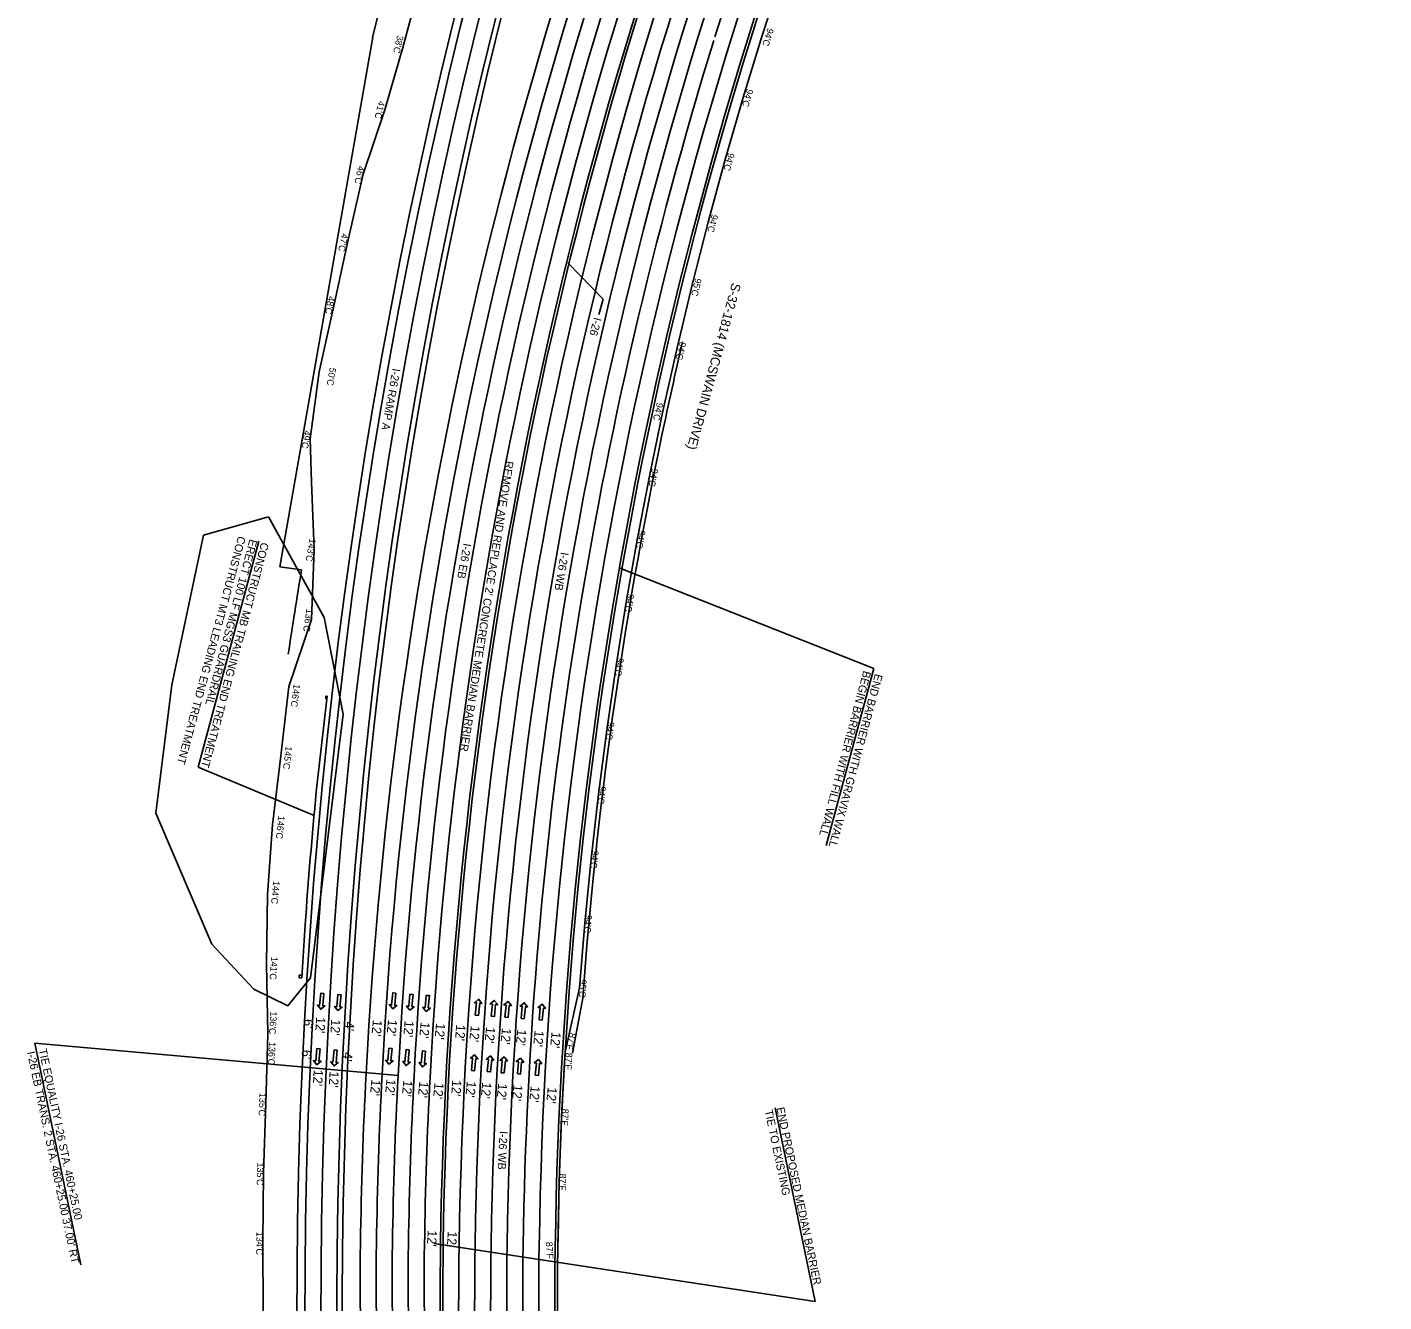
# Model space of a CAD drawing. Extents: x 1966090 to 1975830, y 788086 to 801233.
# Drawn here: x 1966090 to 1967107, y 790893 to 791849 of the extents above; entities that cross this region are included whole.
import ezdxf

# ---------------------------------------------------------------- set-up
doc = ezdxf.new("R2010")
doc.units = 0
for name, color, linetype in [('BR_PRESTRESSED BEAM', 7, 'Continuous'), ('BR_PROPOSED_DRAINAGE', 7, 'Continuous'), ('BR_REBAR', 7, 'Continuous'), ('RD_EX_Driveway_txCode', 7, 'Continuous'), ('RD_EX_RW_TX', 7, 'Continuous'), ('RD_EX_SU_Gas', 7, 'Continuous'), ('RD_EX_SU_H2O', 7, 'Continuous'), ('RD_EX_TX_Dam_ELEV', 7, 'Continuous'), ('RD_PD_PaveShd', 7, 'Continuous'), ('RD_PD_SuperShp1', 7, 'Continuous'), ('RD_Sketch6', 7, 'Continuous'), ('RD_Sketch8', 7, 'Continuous')]:
    doc.layers.add(name, color=color, linetype=linetype)

msp = doc.modelspace()

# ---------------------------------------------------------------- linework, layer by layer
at = {"layer": 'BR_PRESTRESSED BEAM'}
for p, q in [((1966306.7, 791275.8), (1966314.8, 791347.4)), ((1966314.8, 791347.4), (1966313.8, 791347.5)), ((1966313.8, 791347.5), (1966313.8, 791345.5)), ((1966313.8, 791345.5), (1966314.6, 791345.4)), ((1966314.6, 791345.4), (1966314.8, 791347.4)), ((1966298.4, 791176.2), (1966295.8, 791136.3)), ((1966293.8, 791136.4), (1966293.9, 791138.4)), ((1966293.9, 791138.4), (1966295.9, 791138.3)), ((1966295.9, 791138.3), (1966295.8, 791136.3)), ((1966295.8, 791136.3), (1966293.8, 791136.4))]:
    msp.add_line(p, q, dxfattribs=at)
msp.add_arc((1970298.2, 790890.8), 4010, 174.4907, 175.9195, dxfattribs=at)
at = {"layer": 'BR_PROPOSED_DRAINAGE'}
for p, q in [((1966385.1, 791884.3), (1966372.2, 791835.5)), ((1966655.8, 791888.9), (1966640.9, 791842.7)), ((1966640.9, 791842.7), (1966626.7, 791796.2)), ((1966372.2, 791835.5), (1966358.2, 791786.9)), ((1966626.7, 791796.2), (1966613.2, 791749.6)), ((1966358.2, 791786.9), (1966341.9, 791738.7)), ((1966613.2, 791749.6), (1966600.5, 791702.7)), ((1966341.9, 791738.7), (1966330.6, 791689.4)), ((1966600.5, 791702.7), (1966588.4, 791655.7)), ((1966330.6, 791689.4), (1966319.8, 791640)), ((1966588.4, 791655.7), (1966577.1, 791608.5)), ((1966319.8, 791640), (1966308.9, 791590.5)), ((1966577.1, 791608.5), (1966566.5, 791561.1)), ((1966308.9, 791590.5), (1966302.1, 791540.3)), ((1966566.5, 791561.1), (1966556.6, 791513.6)), ((1966303.2, 791507.8), (1966302.1, 791540.3)), ((1966303.2, 791507.8), (1966305.2, 791457.4)), ((1966556.6, 791513.6), (1966547.5, 791465.9)), ((1966547.5, 791465.9), (1966539, 791418)), ((1966305.2, 791457.4), (1966303.2, 791404.9)), ((1966539, 791418), (1966531.4, 791370.1)), ((1966303.2, 791404.9), (1966286.2, 791354.7)), ((1966531.4, 791370.1), (1966524.4, 791322)), ((1966286.2, 791354.7), (1966280.2, 791302.8)), ((1966524.4, 791322), (1966518.2, 791273.9)), ((1966280.2, 791302.8), (1966274, 791250.9)), ((1966518.2, 791273.9), (1966512.7, 791225.6)), ((1966274, 791250.9), (1966270.2, 791198.8)), ((1966512.7, 791225.6), (1966507.9, 791177.3)), ((1966270.2, 791198.8), (1966269.4, 791146.6)), ((1966507.9, 791177.3), (1966503.9, 791128.9)), ((1966269.4, 791146.6), (1966270.4, 791094.3)), ((1966503.9, 791128.9), (1966493.2, 791080.9)), ((1966270.4, 791094.3), (1966268.8, 791042.2)), ((1966493.2, 791080.9), (1966490.6, 791032.3)), ((1966268.8, 791042.2), (1966267.2, 790990.2)), ((1966490.6, 791032.3), (1966488.8, 790983.7)), ((1966267.2, 790990.2), (1966266.7, 790938.1)), ((1966488.8, 790983.7), (1966487.8, 790935)), ((1966266.7, 790938.1), (1966266.9, 790886.1))]:
    msp.add_line(p, q, dxfattribs=at)
msp.add_arc((1969885.9, 790887.5), 3398.5, 179.1982, 182.2683, dxfattribs=at)
at = {"layer": 'BR_REBAR'}
for centre, radius, start, end in [((1969675.5, 790890.4), 3190, 157.1374, 179.2174), ((1969675.5, 790890.4), 3188, 157.1374, 179.2164), ((1969885.9, 790887.5), 3400.5, 179.1982, 182.2683), ((1969885.9, 790887.5), 3398.5, 179.1982, 182.2663)]:
    msp.add_arc(centre, radius, start, end, dxfattribs=at)
at = {"layer": 'RD_EX_Driveway_txCode'}
for points in [[(1966312.4, 791124.6), (1966310, 791124.8), (1966309.1, 791115.7), (1966307.5, 791115.9), (1966310.1, 791112.8), (1966313.2, 791115.3), (1966311.5, 791115.5)], [(1966325.3, 791123.6), (1966322.9, 791123.9), (1966322, 791114.7), (1966320.4, 791114.9), (1966322.9, 791111.8), (1966326, 791114.4), (1966324.4, 791114.5)], [(1966366.4, 791124.9), (1966364, 791125.1), (1966363.1, 791116), (1966361.5, 791116.1), (1966364.1, 791113), (1966367.2, 791115.6), (1966365.5, 791115.7)], [(1966379.3, 791123.9), (1966376.9, 791124.1), (1966376, 791115), (1966374.4, 791115.2), (1966376.9, 791112.1), (1966380, 791114.6), (1966378.4, 791114.8)], [(1966391.5, 791123), (1966389.1, 791123.2), (1966388.2, 791114.1), (1966386.6, 791114.2), (1966389.1, 791111.1), (1966392.2, 791113.7), (1966390.6, 791113.9)], [(1966425.9, 791108.4), (1966428.3, 791108.2), (1966429.2, 791117.3), (1966430.8, 791117.2), (1966428.3, 791120.3), (1966425.2, 791117.7), (1966426.8, 791117.6)], [(1966437.8, 791107.5), (1966440.2, 791107.3), (1966441.1, 791116.4), (1966442.7, 791116.3), (1966440.1, 791119.4), (1966437, 791116.8), (1966438.7, 791116.7)], [(1966448, 791106.8), (1966450.4, 791106.5), (1966451.3, 791115.7), (1966452.9, 791115.5), (1966450.4, 791118.6), (1966447.3, 791116), (1966448.9, 791115.9)], [(1966460.2, 791105.8), (1966462.6, 791105.6), (1966463.5, 791114.7), (1966465.1, 791114.6), (1966462.6, 791117.7), (1966459.5, 791115.1), (1966461.1, 791115)], [(1966473.7, 791104.8), (1966476.1, 791104.6), (1966477, 791113.7), (1966478.6, 791113.6), (1966476, 791116.7), (1966473, 791114.1), (1966474.6, 791114)], [(1966309.5, 791083.1), (1966307.1, 791083.3), (1966306.3, 791074.2), (1966304.6, 791074.3), (1966307.2, 791071.2), (1966310.3, 791073.8), (1966308.6, 791073.9)], [(1966322.4, 791082.1), (1966320, 791082.3), (1966319.1, 791073.2), (1966317.5, 791073.4), (1966320, 791070.3), (1966323.1, 791072.8), (1966321.5, 791073)], [(1966363.5, 791083.3), (1966361.1, 791083.6), (1966360.3, 791074.4), (1966358.6, 791074.6), (1966361.2, 791071.5), (1966364.3, 791074), (1966362.6, 791074.2)], [(1966376.4, 791082.4), (1966374, 791082.6), (1966373.1, 791073.5), (1966371.5, 791073.6), (1966374, 791070.5), (1966377.1, 791073.1), (1966375.5, 791073.2)], [(1966388.6, 791081.4), (1966386.2, 791081.7), (1966385.3, 791072.5), (1966383.7, 791072.7), (1966386.3, 791069.6), (1966389.3, 791072.2), (1966387.7, 791072.3)], [(1966423, 791066.9), (1966425.4, 791066.7), (1966426.3, 791075.8), (1966427.9, 791075.6), (1966425.4, 791078.7), (1966422.3, 791076.2), (1966423.9, 791076)], [(1966434.9, 791066), (1966437.3, 791065.8), (1966438.2, 791074.9), (1966439.8, 791074.7), (1966437.2, 791077.8), (1966434.2, 791075.3), (1966435.8, 791075.1)], [(1966445.2, 791065.2), (1966447.5, 791065), (1966448.4, 791074.1), (1966450, 791074), (1966447.5, 791077.1), (1966444.4, 791074.5), (1966446, 791074.4)], [(1966457.4, 791064.3), (1966459.7, 791064.1), (1966460.6, 791073.2), (1966462.2, 791073), (1966459.7, 791076.1), (1966456.6, 791073.6), (1966458.2, 791073.4)], [(1966470.8, 791063.3), (1966473.2, 791063.1), (1966474.1, 791072.2), (1966475.7, 791072), (1966473.2, 791075.1), (1966470.1, 791072.6), (1966471.7, 791072.4)]]:
    msp.add_lwpolyline(points, close=True, dxfattribs=at)
at = {"layer": 'RD_EX_SU_Gas'}
for centre, radius, start, end in [((1970298.2, 790890.8), 3988, 153.1374, 186.3991), ((1969675.5, 790890.4), 3312, 157.822, 177.0114), ((1969675.5, 790890.4), 3300, 157.822, 177.0114), ((1969675.5, 790890.4), 3214, 157.1374, 162.7868), ((1969675.5, 790890.4), 3250, 157.8325, 179.1982), ((1969675.5, 790890.4), 3238, 157.8325, 179.1982), ((1969675.5, 790890.4), 3226, 157.8325, 179.1982), ((1969675.5, 790890.4), 3214, 162.8366, 179.1982), ((1969675.5, 790890.4), 3312, 177.0114, 179.1982), ((1969675.5, 790890.4), 3300, 177.0114, 179.1982), ((1968216.3, 790910.8), 1852.7, 179.1982, 183.4866), ((1968216.3, 790910.8), 1840.7, 179.1982, 183.4866), ((1969885.9, 790887.5), 3460.5, 179.1982, 191.7117), ((1969885.9, 790887.5), 3448.5, 179.1982, 191.7117), ((1969885.9, 790887.5), 3436.5, 179.1982, 184.4912), ((1969885.9, 790887.5), 3424.5, 179.1982, 184.4912)]:
    msp.add_arc(centre, radius, start, end, dxfattribs=at)
at = {"layer": 'RD_EX_TX_Dam_ELEV'}
for p, q in [((1966349, 791841.3), (1966279.3, 791444.3)), ((1966565.2, 791540.7), (1966565.8, 791543.2)), ((1966295.6, 791442.1), (1966279.3, 791444.3)), ((1966506.4, 791121.2), (1966498.7, 791079.8))]:
    msp.add_line(p, q, dxfattribs=at)
for centre, radius, start, end in [((1970298.2, 790890.8), 4062, 153.0951, 166.4711), ((1969675.5, 790890.4), 3177.5, 166.8537, 168.1442), ((1969675.5, 790890.4), 3177.5, 168.1907, 175.8341), ((1969666.1, 790880.5), 3416.9, 170.5396, 171.6135)]:
    msp.add_arc(centre, radius, start, end, dxfattribs=at)
at = {"layer": 'RD_PD_PaveShd'}
msp.add_line((1966401.8, 790936.2), (1966399.8, 790936.3), dxfattribs=at)
for centre, radius, start, end in [((1970298.2, 790890.8), 4006, 153.1374, 186.3991), ((1970298.2, 790890.8), 3972, 153.1374, 186.1282), ((1969675.5, 790890.4), 3336, 157.1374, 177.0114), ((1969675.5, 790890.4), 3276, 157.1374, 179.1982), ((1969675.5, 790890.4), 3274, 157.1374, 179.1982), ((1969675.5, 790890.4), 3190, 157.1374, 179.2174), ((1969675.5, 790890.4), 3336, 177.0114, 179.1982), ((1968216.3, 790910.8), 1876.7, 179.1982, 183.4866), ((1969675.5, 790890.4), 3276, 179.1982, 191.7117), ((1969675.5, 790890.4), 3274, 179.1982, 191.7117), ((1969885.9, 790887.5), 3400.5, 179.1982, 182.2683)]:
    msp.add_arc(centre, radius, start, end, dxfattribs=at)
at = {"layer": 'RD_PD_SuperShp1'}
msp.add_arc((1966773.3, 790734.6), 333.5, 177.186, 177.186, dxfattribs=at)
at = {"layer": 'RD_Sketch6'}
for p, q in [((1966521.6, 791645.1), (1966495.2, 791672.3)), ((1966518.5, 791633.5), (1966521.6, 791645.1)), ((1966263.7, 791463.6), (1966218.1, 791294.3)), ((1966533.8, 791443.6), (1966724.5, 791368.2)), ((1966688.8, 791235.5), (1966724.5, 791368.2)), ((1966218.1, 791294.3), (1966305.1, 791258.1)), ((1966095.7, 791087.4), (1966368, 791063.1)), ((1966130.2, 790921.1), (1966095.7, 791087.4)), ((1966680.7, 790893.7), (1966650.6, 791038.9)), ((1966395, 790937.3), (1966680.7, 790893.7))]:
    msp.add_line(p, q, dxfattribs=at)
msp.add_lwpolyline([(1966270.9, 791481.9), (1966312.5, 791406.4), (1966326.9, 791334), (1966302.4, 791136.4), (1966285.3, 791115.4), (1966259.8, 791127.8), (1966228.5, 791161.6), (1966186.5, 791259.7), (1966198.5, 791356), (1966222.3, 791468.1)], close=True, dxfattribs=at)
at = {"layer": 'RD_Sketch8'}
for centre, radius, start, end in [((1970298.2, 790890.8), 4000, 153.1374, 186.3991), ((1970298.2, 790890.8), 3976, 153.1374, 186.1303), ((1969675.5, 790890.4), 3324, 157.1374, 177.0114), ((1969675.5, 790890.4), 3288, 157.1374, 177.0114), ((1969675.5, 790890.4), 3262, 157.1374, 179.1982), ((1969675.5, 790890.4), 3202, 157.1374, 179.1982), ((1969675.5, 790890.4), 3324, 177.0114, 179.1982), ((1969675.5, 790890.4), 3288, 177.0114, 179.1982), ((1968216.3, 790910.8), 1864.7, 179.1982, 183.4866), ((1968216.3, 790910.8), 1828.7, 179.1982, 183.4866), ((1969885.9, 790887.5), 3472.5, 179.1982, 191.7117), ((1969885.9, 790887.5), 3412.5, 179.1982, 184.4912)]:
    msp.add_arc(centre, radius, start, end, dxfattribs=at)

# ---------------------------------------------------------------- texts
at = {"layer": 'RD_EX_Driveway_txCode'}
for s, height, rotation, p in [('I-26 RAMP A', 6, 259.7492, (1966363.9, 791593.5)), ("REMOVE AND REPLACE 2' CONCRETE MEDIAN BARRIER", 6, 261.0168, (1966448.7, 791524.1)), ("6'", 7, 269.0379, (1966297.3, 791105.4)), ("12'", 7, 266.9771, (1966306.6, 791107.1)), ("12'", 7, 266.9771, (1966317.9, 791105.4)), ("4'", 7, 266.9056, (1966328.3, 791103.6)), ("12'", 7, 264.5562, (1966349.2, 791105)), ("12'", 7, 264.5562, (1966360.5, 791105.3)), ("12'", 7, 264.5562, (1966373, 791104.4)), ("12'", 7, 264.5562, (1966385, 791103.5)), ("12'", 7, 264.5562, (1966396.5, 791102.6)), ("12'", 7, 266.5124, (1966411.5, 791101.4)), ("12'", 7, 264.5562, (1966422.5, 791100.7)), ("12'", 7, 264.5562, (1966434, 791099.8)), ("12'", 7, 264.5562, (1966445.9, 791098.9)), ("12'", 7, 264.5562, (1966457.4, 791098)), ("12'", 7, 264.5562, (1966470.4, 791097.1)), ("12'", 7, 264.5562, (1966483.1, 791096.1)), ("6'", 7, 269.0379, (1966295.9, 791082.4)), ("4'", 7, 266.9056, (1966326.9, 791080.7)), ("12'", 7, 266.9771, (1966304.8, 791067.6)), ("12'", 7, 266.9771, (1966316.7, 791066.4)), ("12'", 7, 264.5562, (1966348.1, 791060.4)), ("12'", 7, 264.5562, (1966359.4, 791060.7)), ("12'", 7, 264.5562, (1966372, 791059.8)), ("12'", 7, 264.5562, (1966384, 791058.9)), ("12'", 7, 264.5562, (1966395.4, 791058)), ("12'", 7, 266.5124, (1966408.6, 791059.9)), ("12'", 7, 264.5562, (1966419.6, 791059.1)), ("12'", 7, 264.5562, (1966431.1, 791058.3)), ("12'", 7, 264.5562, (1966443, 791057.4)), ("12'", 7, 264.5562, (1966454.5, 791056.5)), ("12'", 7, 264.5562, (1966467.5, 791055.5)), ("12'", 7, 264.5562, (1966480.2, 791054.6)), ("12'", 7, 266.5124, (1966390.3, 790947.3)), ("12'", 7, 266.5124, (1966405.3, 790946.6))]:
    msp.add_text(s, height=height, rotation=rotation, dxfattribs=at).set_placement(p)
at = {"layer": 'RD_EX_RW_TX'}
for s, rotation, p in [("38'C", 256.4711, (1966367.4, 791843.1)), ("94'C", 252.5781, (1966644.9, 791848.5)), ("94'C", 253.4528, (1966629.5, 791803)), ("41'C", 257.1873, (1966353.4, 791794)), ("94'C", 254.3276, (1966615.5, 791755.1)), ("46'C", 257.9035, (1966338.1, 791745.2)), ("94'C", 255.2023, (1966603.1, 791708.9)), ("47'C", 258.6197, (1966325.8, 791694.5)), ("95'C", 256.0771, (1966590.8, 791661.1)), ("48'C", 259.3359, (1966315.7, 791647.6)), ("94'C", 256.9518, (1966579.1, 791613.3)), ("50'C", 260.0521, (1966316.8, 791594)), ("94'C", 257.8265, (1966561.9, 791567.8)), ("49'C", 260.7683, (1966297.7, 791546.9)), ("94'C", 258.7013, (1966558.2, 791518.4)), ("143'C", 260.4508, (1966301.6, 791465.8)), ("94'C", 259.576, (1966548.6, 791472.2)), ("94'C", 260.4508, (1966540.1, 791424.4)), ("136'C", 261.3255, (1966299.4, 791413.2)), ("94'C", 261.3255, (1966532.3, 791376.4)), ("146'C", 262.2003, (1966289.8, 791356.7)), ("94'C", 262.2003, (1966525.3, 791328.4)), ("145'C", 263.075, (1966283.8, 791310.1)), ("94'C", 263.075, (1966518.9, 791280.2)), ("146'C", 263.9498, (1966278.2, 791257.9)), ("94'C", 263.9498, (1966513.4, 791232)), ("144'C", 264.8245, (1966274.4, 791209.1)), ("94'C", 264.8245, (1966508.5, 791183.7)), ("141'C", 265.6993, (1966273, 791152.3)), ("95'C", 265.6993, (1966504.4, 791135.3)), ("136'C", 266.574, (1966272.3, 791111.3)), ("136'C", 266.574, (1966271.4, 791088.3)), ("87'F", 257.4493, (1966496.6, 791095.4)), ("87'F", 266.574, (1966493.7, 791080.3)), ("135'C", 267.4487, (1966264.2, 791050.1)), ("87'F", 267.4487, (1966490.9, 791038.3)), ("135'C", 268.3235, (1966262.5, 790998)), ("87'F", 268.3235, (1966489, 790989.7)), ("134'C", 269.1982, (1966261.9, 790945.9)), ("87'F", 273.3863, (1966478.7, 790938.3))]:
    msp.add_text(s, height=5, rotation=rotation, dxfattribs=at).set_placement(p)
at = {"layer": 'RD_EX_SU_H2O'}
for s, height, rotation, p in [('S-32-1814 (MCSWAIN DRIVE)', 7, 254.761, (1966618.3, 791657.7)), ('I-26 EB', 6, 259.6156, (1966417.1, 791462.4)), ('I-26 WB', 6, 260.5935, (1966490, 791455.7)), ('I-26 WB', 6, 267.1179, (1966444.1, 791021.6))]:
    msp.add_text(s, height=height, rotation=rotation, dxfattribs=at).set_placement(p)
at = {"layer": 'RD_Sketch6'}
for s, rotation, p in [('I-26', 254.9393, (1966514.9, 791631.8)), ('CONSTRUCT MT3 LEADING END TREATMENT', 254.9659, (1966248.1, 791467.8)), ('ERECT 100 LF MGS3 GUARDRAIL', 254.9659, (1966256.8, 791465.5)), ('CONSTRUCT MB TRAILING END TREATMENT', 254.9659, (1966265.5, 791463.1)), ('BEGIN BARRIER WITH FILL WALL', 254.9449, (1966716.8, 791366.9)), ('END BARRIER WITH GRAVIX WALL', 254.9449, (1966725.5, 791364.6)), ("I-26 EB TRANS. 2 STA. 460+25.00 37.00' RT", 281.8716, (1966089.9, 791080.6)), ('TIE EQUALITY I-26 STA. 460+25.00', 281.8716, (1966098.7, 791082.5)), ('TIE TO EXISTING', 281.8716, (1966642.7, 791036.8)), ('END PROPOSED MEDIAN BARRIER', 281.8716, (1966651.5, 791038.7))]:
    msp.add_text(s, height=6, rotation=rotation, dxfattribs=at).set_placement(p)

doc.saveas('drawing.dxf')
